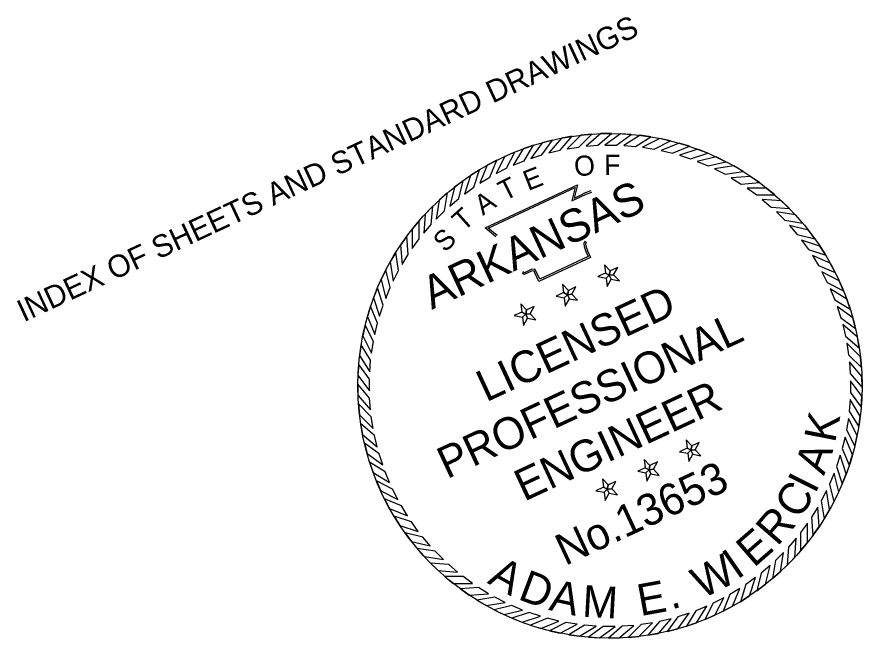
# Model space of a CAD drawing. Extents: x 756526 to 763735, y 1656374 to 1661090.
# Drawn here: x 758870.1 to 759272.4, y 1658719 to 1659014.4 of the extents above; entities that cross this region are included whole.
import ezdxf

# ---------------------------------------------------------------- set-up
doc = ezdxf.new("R2010")
doc.units = 0
for name, color, linetype in [('1', 7, 'Continuous'), ('G-ANNO-STMP', 7, 'Continuous'), ('G-No Plot-Stamp-1', 7, 'Continuous')]:
    doc.layers.add(name, color=color, linetype=linetype)

msp = doc.modelspace()

# ---------------------------------------------------------------- linework, layer by layer
at = {"layer": 'G-ANNO-STMP'}
for points in [[(759143.7, 1658958.67), (759138.57, 1658958.18), (759132.06, 1658951.68), (759137.57, 1658952.53)], [(759153.12, 1658958.98), (759147.96, 1658958.9), (759140.97, 1658952.93), (759146.53, 1658953.35)], [(759162.53, 1658958.55), (759157.38, 1658958.87), (759149.94, 1658953.47), (759155.52, 1658953.45)], [(759125.09, 1658955.84), (759120.09, 1658954.56), (759114.68, 1658947.12), (759119.99, 1658948.82)], [(759134.34, 1658957.62), (759129.25, 1658956.73), (759123.28, 1658949.74), (759128.71, 1658951.02)], [(759171.88, 1658957.38), (759166.78, 1658958.11), (759158.93, 1658953.31), (759164.49, 1658952.85)], [(759181.11, 1658955.48), (759176.08, 1658956.61), (759167.88, 1658952.44), (759173.39, 1658951.55)], [(759190.17, 1658952.87), (759185.24, 1658954.39), (759176.74, 1658950.87), (759182.16, 1658949.55)], [(759116, 1658953.34), (759111.12, 1658951.67), (759106.31, 1658943.83), (759111.47, 1658945.94)], [(759198.99, 1658949.55), (759194.19, 1658951.45), (759185.44, 1658948.61), (759190.74, 1658946.87)], [(759098.56, 1658946.24), (759094, 1658943.83), (759090.48, 1658935.33), (759095.24, 1658938.23)], [(759107.14, 1658950.13), (759102.4, 1658948.09), (759098.23, 1658939.89), (759103.2, 1658942.41)], [(759207.52, 1658945.55), (759202.89, 1658947.83), (759193.94, 1658945.68), (759199.09, 1658943.53)], [(759215.71, 1658940.9), (759211.27, 1658943.53), (759202.19, 1658942.09), (759207.15, 1658939.54)], [(759090.31, 1658941.69), (759085.95, 1658938.93), (759083.11, 1658930.18), (759087.63, 1658933.44)], [(759223.51, 1658935.61), (759219.29, 1658938.58), (759210.12, 1658937.86), (759214.87, 1658934.93)], [(759082.44, 1658936.5), (759078.31, 1658933.41), (759076.16, 1658924.46), (759080.41, 1658928.07)], [(759075, 1658930.72), (759071.13, 1658927.31), (759069.69, 1658918.22), (759073.65, 1658922.15)], [(759230.88, 1658929.73), (759226.9, 1658933.02), (759217.7, 1658933.02), (759222.2, 1658929.73)], [(759237.76, 1658923.29), (759234.05, 1658926.89), (759224.88, 1658927.61), (759229.11, 1658923.97)], [(759068.04, 1658924.37), (759064.45, 1658920.66), (759063.73, 1658911.49), (759067.36, 1658915.72)], [(759244.11, 1658916.33), (759240.7, 1658920.21), (759231.61, 1658921.64), (759235.54, 1658917.69)], [(759061.6, 1658917.49), (759058.31, 1658913.51), (759058.31, 1658904.31), (759061.6, 1658908.81)], [(759249.89, 1658908.9), (759246.8, 1658913.02), (759237.85, 1658915.17), (759241.46, 1658910.92)], [(759055.72, 1658910.12), (759052.75, 1658905.9), (759053.47, 1658896.73), (759056.4, 1658901.48)], [(759255.08, 1658901.03), (759252.32, 1658905.39), (759243.57, 1658908.23), (759246.83, 1658903.71)], [(759050.44, 1658902.32), (759047.81, 1658897.88), (759049.25, 1658888.8), (759051.79, 1658893.76)], [(759259.63, 1658892.78), (759257.22, 1658897.34), (759248.72, 1658900.86), (759251.62, 1658896.1)], [(759045.78, 1658894.13), (759043.51, 1658889.5), (759045.66, 1658880.55), (759047.81, 1658885.7)], [(759152.05, 1658891.56), (759152.45, 1658893.61), (759149.74, 1658896.53), (759150.22, 1658892.57)], [(759152.05, 1658891.56), (759154.13, 1658891.81), (759156.07, 1658895.3), (759152.45, 1658893.61)], [(759152.05, 1658891.56), (759150.22, 1658892.57), (759146.61, 1658890.89), (759150.52, 1658890.13)], [(759152.05, 1658891.56), (759150.52, 1658890.13), (759151.01, 1658886.17), (759152.94, 1658889.66)], [(759152.05, 1658891.56), (759152.94, 1658889.66), (759156.85, 1658888.9), (759154.13, 1658891.81)], [(759263.52, 1658884.2), (759261.48, 1658888.93), (759253.28, 1658893.11), (759255.8, 1658888.13)], [(759132.17, 1658882.28), (759132.57, 1658884.34), (759129.85, 1658887.25), (759130.33, 1658883.3)], [(759132.17, 1658882.28), (759134.25, 1658882.54), (759136.18, 1658886.02), (759132.57, 1658884.34)], [(759041.78, 1658885.6), (759039.88, 1658880.8), (759042.72, 1658872.05), (759044.46, 1658877.35)], [(759132.17, 1658882.28), (759130.33, 1658883.3), (759126.72, 1658881.61), (759130.63, 1658880.85)], [(759132.17, 1658882.28), (759130.63, 1658880.85), (759131.12, 1658876.9), (759133.05, 1658880.38)], [(759132.17, 1658882.28), (759133.05, 1658880.38), (759136.96, 1658879.62), (759134.25, 1658882.54)], [(759266.73, 1658875.33), (759265.06, 1658880.22), (759257.22, 1658885.02), (759259.33, 1658879.87)], [(759112.28, 1658873.01), (759112.68, 1658875.07), (759109.96, 1658877.98), (759110.45, 1658874.02)], [(759038.47, 1658876.78), (759036.95, 1658871.85), (759040.47, 1658863.35), (759041.78, 1658868.77)], [(759112.28, 1658873.01), (759110.45, 1658874.02), (759106.83, 1658872.34), (759110.75, 1658871.58)], [(759112.28, 1658873.01), (759114.36, 1658873.26), (759116.29, 1658876.75), (759112.68, 1658875.07)], [(759269.23, 1658866.25), (759267.95, 1658871.25), (759260.51, 1658876.66), (759262.21, 1658871.35)], [(759112.28, 1658873.01), (759110.75, 1658871.58), (759111.23, 1658867.62), (759113.16, 1658871.11)], [(759112.28, 1658873.01), (759113.16, 1658871.11), (759117.08, 1658870.35), (759114.36, 1658873.26)], [(759035.85, 1658867.72), (759034.72, 1658862.69), (759038.9, 1658854.49), (759039.79, 1658860)], [(759271.01, 1658857), (759270.12, 1658862.08), (759263.13, 1658868.05), (759264.41, 1658862.63)], [(759033.95, 1658858.49), (759033.22, 1658853.39), (759038.03, 1658845.54), (759038.48, 1658851.1)], [(759272.06, 1658847.63), (759271.57, 1658852.77), (759265.07, 1658859.27), (759265.92, 1658853.76)], [(759272.37, 1658838.21), (759272.29, 1658843.37), (759266.32, 1658850.37), (759266.74, 1658844.81)], [(759032.79, 1658849.14), (759032.46, 1658843.99), (759037.87, 1658836.55), (759037.88, 1658842.13)], [(759032.36, 1658839.73), (759032.44, 1658834.57), (759038.41, 1658827.58), (759037.99, 1658833.14)], [(759271.94, 1658828.8), (759272.27, 1658833.95), (759266.86, 1658841.39), (759266.84, 1658835.82)], [(759032.67, 1658830.31), (759033.15, 1658825.18), (759039.65, 1658818.67), (759038.8, 1658824.18)], [(759270.77, 1658819.45), (759271.5, 1658824.56), (759266.7, 1658832.4), (759266.24, 1658826.84)], [(759268.87, 1658810.22), (759270, 1658815.26), (759265.83, 1658823.45), (759264.94, 1658817.95)], [(759033.72, 1658820.95), (759034.6, 1658815.86), (759041.6, 1658809.89), (759040.31, 1658815.32)], [(759266.26, 1658801.17), (759267.78, 1658806.1), (759264.26, 1658814.6), (759262.94, 1658809.18)], [(759035.5, 1658811.7), (759036.78, 1658806.7), (759044.22, 1658801.29), (759042.51, 1658806.6)], [(759190.89, 1658808.27), (759191.29, 1658810.33), (759188.57, 1658813.25), (759189.06, 1658809.29)], [(759190.89, 1658808.27), (759192.97, 1658808.53), (759194.9, 1658812.02), (759191.29, 1658810.33)], [(759190.89, 1658808.27), (759189.06, 1658809.29), (759185.44, 1658807.61), (759189.36, 1658806.85)], [(759190.89, 1658808.27), (759189.36, 1658806.85), (759189.84, 1658802.89), (759191.78, 1658806.38)], [(759190.89, 1658808.27), (759191.78, 1658806.38), (759195.69, 1658805.61), (759192.97, 1658808.53)], [(759262.94, 1658792.35), (759264.84, 1658797.14), (759262, 1658805.89), (759260.26, 1658800.6)], [(759038, 1658802.61), (759039.67, 1658797.73), (759047.51, 1658792.92), (759045.39, 1658798.08)], [(759171, 1658799), (759171.4, 1658801.06), (759168.68, 1658803.97), (759169.17, 1658800.02)], [(759171, 1658799), (759173.08, 1658799.26), (759175.01, 1658802.74), (759171.4, 1658801.06)], [(759171, 1658799), (759169.17, 1658800.02), (759165.56, 1658798.33), (759169.47, 1658797.57)], [(759171, 1658799), (759169.47, 1658797.57), (759169.95, 1658793.62), (759171.89, 1658797.1)], [(759171, 1658799), (759171.89, 1658797.1), (759175.8, 1658796.34), (759173.08, 1658799.26)], [(759258.94, 1658783.82), (759261.22, 1658788.45), (759259.07, 1658797.39), (759256.92, 1658792.25)], [(759041.2, 1658793.75), (759043.25, 1658789.01), (759051.44, 1658784.84), (759048.93, 1658789.81)], [(759151.11, 1658789.73), (759151.51, 1658791.78), (759148.8, 1658794.7), (759149.28, 1658790.74)], [(759151.11, 1658789.73), (759153.19, 1658789.98), (759155.13, 1658793.47), (759151.51, 1658791.78)], [(759151.11, 1658789.73), (759149.28, 1658790.74), (759145.67, 1658789.06), (759149.58, 1658788.3)], [(759151.11, 1658789.73), (759149.58, 1658788.3), (759150.07, 1658784.34), (759152, 1658787.83)], [(759151.11, 1658789.73), (759152, 1658787.83), (759155.91, 1658787.07), (759153.19, 1658789.98)], [(759254.29, 1658775.62), (759256.92, 1658780.06), (759255.48, 1658789.15), (759252.93, 1658784.19)], [(759045.09, 1658785.17), (759047.51, 1658780.61), (759056, 1658777.09), (759053.11, 1658781.85)], [(759249, 1658767.82), (759251.97, 1658772.04), (759251.25, 1658781.21), (759248.32, 1658776.47)], [(759049.64, 1658776.92), (759052.41, 1658772.56), (759061.16, 1658769.72), (759057.89, 1658774.24)], [(759243.12, 1658760.46), (759246.41, 1658764.43), (759246.41, 1658773.63), (759243.12, 1658769.13)], [(759054.83, 1658769.05), (759057.93, 1658764.92), (759066.87, 1658762.77), (759063.26, 1658767.02)], [(759236.68, 1658753.58), (759240.28, 1658757.28), (759241, 1658766.45), (759237.36, 1658762.23)], [(759060.62, 1658761.61), (759064.03, 1658757.74), (759073.11, 1658756.3), (759069.18, 1658760.26)], [(759229.72, 1658747.23), (759233.6, 1658750.64), (759235.03, 1658759.72), (759231.08, 1658755.79)], [(759066.97, 1658754.65), (759070.67, 1658751.06), (759079.84, 1658750.34), (759075.62, 1658753.97)], [(759222.29, 1658741.44), (759226.41, 1658744.54), (759228.56, 1658753.48), (759224.31, 1658749.87)], [(759073.85, 1658748.21), (759077.82, 1658744.92), (759087.02, 1658744.92), (759082.52, 1658748.21)], [(759214.42, 1658736.25), (759218.78, 1658739.02), (759221.62, 1658747.77), (759217.1, 1658744.5)], [(759081.21, 1658742.33), (759085.43, 1658739.36), (759094.6, 1658740.08), (759089.86, 1658743.01)], [(759206.17, 1658731.7), (759210.73, 1658734.11), (759214.25, 1658742.61), (759209.49, 1658739.72)], [(759089.01, 1658737.05), (759093.45, 1658734.42), (759102.54, 1658735.86), (759097.58, 1658738.4)], [(759197.59, 1658727.81), (759202.32, 1658729.86), (759206.5, 1658738.05), (759201.52, 1658735.54)], [(759097.21, 1658732.39), (759101.84, 1658730.12), (759110.78, 1658732.27), (759105.64, 1658734.42)], [(759188.72, 1658724.61), (759193.61, 1658726.28), (759198.41, 1658734.12), (759193.26, 1658732)], [(759105.74, 1658728.39), (759110.53, 1658726.49), (759119.28, 1658729.33), (759113.99, 1658731.07)], [(759179.64, 1658722.11), (759184.64, 1658723.39), (759190.05, 1658730.83), (759184.74, 1658729.12)], [(759114.56, 1658725.08), (759119.49, 1658723.56), (759127.99, 1658727.08), (759122.57, 1658728.39)], [(759123.61, 1658722.46), (759128.65, 1658721.33), (759136.84, 1658725.51), (759131.34, 1658726.4)], [(759132.84, 1658720.56), (759137.95, 1658719.83), (759145.79, 1658724.64), (759140.23, 1658725.09)], [(759151.6, 1658718.97), (759156.76, 1658719.05), (759163.76, 1658725.02), (759158.2, 1658724.6)], [(759161.02, 1658719.28), (759166.16, 1658719.76), (759172.66, 1658726.26), (759167.15, 1658725.41)], [(759170.39, 1658720.33), (759175.47, 1658721.21), (759181.44, 1658728.2), (759176.02, 1658726.92)], [(759142.19, 1658719.4), (759147.34, 1658719.07), (759154.78, 1658724.48), (759149.21, 1658724.49)]]:
    msp.add_lwpolyline(points, close=True, dxfattribs=at)
for points in [[(759098.13, 1658909.79), (759093.03, 1658914.09), (759136.89, 1658934.58), (759135.37, 1658928.26), (759138.33, 1658929.69), (759140.81, 1658930.88), (759143.42, 1658931.77)], [(759098.62, 1658910.37), (759094.44, 1658913.91), (759135.77, 1658933.21), (759134.25, 1658926.87), (759138.67, 1658929), (759141.1, 1658930.17), (759143.67, 1658931.05)], [(759141.12, 1658907.45), (759140.66, 1658906.5), (759140.83, 1658905.47), (759141.65, 1658903.08), (759143.06, 1658900.05), (759118.57, 1658888.63), (759116.66, 1658892.72), (759116.24, 1658893.63), (759115.1, 1658893.47), (759111.62, 1658891.85), (759110.56, 1658892.5)], [(759140.43, 1658907.79), (759139.86, 1658906.61), (759140.09, 1658905.28), (759140.93, 1658902.79), (759142.04, 1658900.42), (759118.94, 1658889.65), (759117.36, 1658893.05), (759116.69, 1658894.47), (759114.88, 1658894.21), (759111.67, 1658892.72), (759110.96, 1658893.15)]]:
    msp.add_lwpolyline(points, dxfattribs=at)
at = {"layer": 'G-No Plot-Stamp-1'}
msp.add_circle((759152.36, 1658838.97), 120, dxfattribs=at)

# ---------------------------------------------------------------- texts
at = {"layer": '1'}
msp.add_text('INDEX OF SHEETS AND STANDARD DRAWINGS', height=10.5516, rotation=25, dxfattribs=at).set_placement((758873.41, 1658869.12))
at = {"layer": 'G-ANNO-STMP'}
for s, height, rotation, p in [('O', 9.55, 6.2218, (759135.83, 1658938.39)), ('F', 9.55, 0.3628, (759149.62, 1658939.27)), ('E', 9.55, 21.672, (759113.44, 1658931.56)), ('T', 9.55, 26.4789, (759102.24, 1658926.66)), ('ARKANSAS', 15.584, 25, (759067.57, 1658875.07)), ('A', 9.55, 33.6788, (759091.87, 1658919.72)), ('T', 9.55, 41.9015, (759082.64, 1658912.08)), ('S', 9.55, 44.7726, (759073.94, 1658902.01)), ('LICENSED', 15.087, 25, (759093.45, 1658831.02)), ('PROFESSIONAL', 15.0867, 25, (759074.81, 1658794.49)), ('ENGINEER', 15.087, 25, (759111.52, 1658783.77)), ('K', 15.09, 78.8471, (759259.48, 1658811.45)), ('A', 15.09, 70.185, (759254.23, 1658795.95)), ('No.13653', 15.027, 25, (759131.04, 1658753.18)), ('I', 15.09, 63.4057, (759249.92, 1658787.18)), ('C', 15.09, 57.1396, (759242.43, 1658774.89)), ('R', 15.09, 49.1616, (759232.01, 1658762.26)), ('E', 15.09, 41.0125, (759220.83, 1658752.18)), ('W', 15.09, 27.1127, (759196.22, 1658737.37)), ('I', 15.09, 34.5753, (759212.85, 1658746.55)), ('A', 15.09, 330.982, (759093.6, 1658745.3)), ('D', 15.09, 339.3022, (759108.08, 1658737.66)), ('A', 15.09, 347.6223, (759122.88, 1658732.39)), ('E', 15.09, 10.2782, (759166.86, 1658729.38)), ('M', 15.09, 356.7969, (759138.93, 1658729.13)), ('.', 15.09, 15.8583, (759181.58, 1658732.48))]:
    msp.add_text(s, height=height, rotation=rotation, dxfattribs=at).set_placement(p)

doc.saveas('drawing.dxf')
